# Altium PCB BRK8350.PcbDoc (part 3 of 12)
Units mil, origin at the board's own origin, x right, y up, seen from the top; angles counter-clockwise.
Board outline 9448.82 x 5905.51 mil, 8 copper layers (L1-TOP, L2-GND, L3-SIG, L4-GND, L5-PWR, L6-PWR, L7-GND, L8-BOT), stack 57.69 mil thick; 288 components, 543 nets, 1891 pads, 2032 vias.
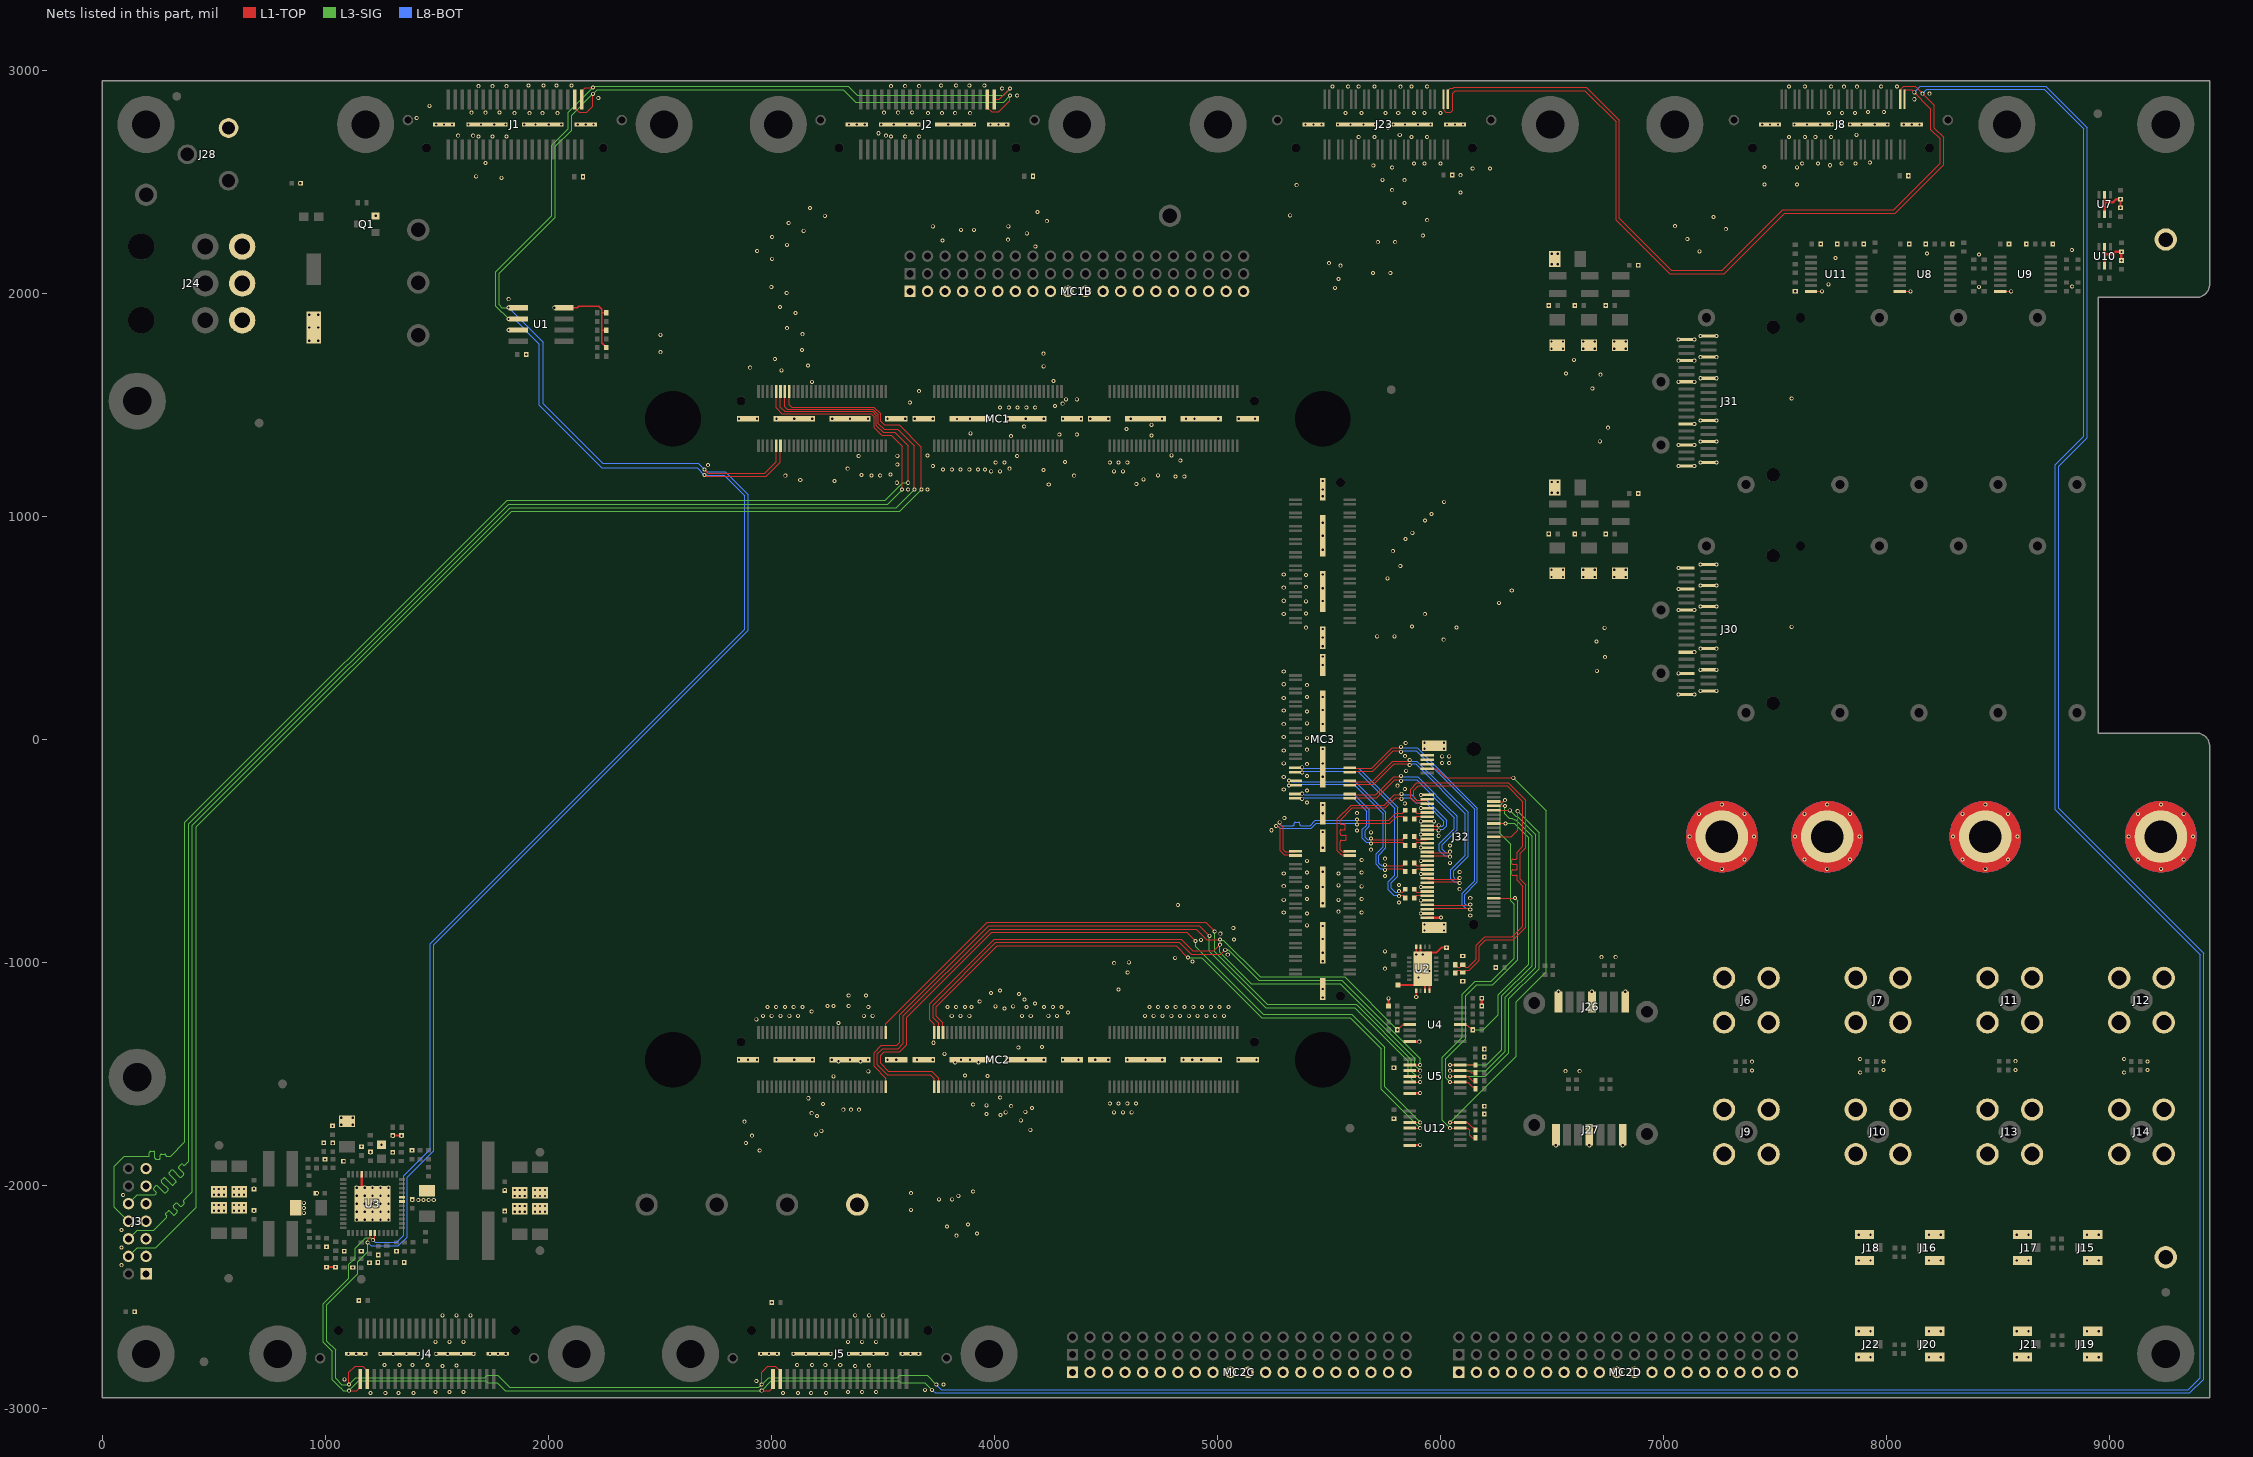
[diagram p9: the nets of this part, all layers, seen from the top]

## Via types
v1: diameter 18, hole 10, L1-TOP to L8-BOT, tented both sides, 2032 vias

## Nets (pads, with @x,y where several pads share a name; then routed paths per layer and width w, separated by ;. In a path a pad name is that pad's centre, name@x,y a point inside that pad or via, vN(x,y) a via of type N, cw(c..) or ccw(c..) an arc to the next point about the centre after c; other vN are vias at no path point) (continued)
DGND: C1.1 C2.1 C3.1 C4.1 C5.1 C30.1 C31.1 C32.1 C33.2 C34.2 C36.2 C37.1 C38.1 C39.1 C40.1 C42.2 C43.2 C44.2 C46.2 C47.2 C48.1 C49.1 C50.1 C51.1 C53.2 C54.2 C55.2 C57.2 C58.2 C59.1 C60.1 C61.1 C63.2 C64.2 C65.2 C67.1 C68.1 C69.1 C72.2 C73.1 C74.2 C75.1 C76.1 C85.1 C86.1 C87.1 C88.1 C89.1 C90.1 C91.1 C92.1 C93.1 C94.1 C95.1 C96.1 C97.1 C98.1 C99.1 C100.1 C101.1 C102.1 C103.1 C104.1 C105.1 C106.1 C107.1 C108.1 C109.1 C110.1 C111.1 C112.1 C113.1 C114.1 C115.1 C116.1 C117.1 C118.1 C119.1 J1.0 J2.0 J3.1 J3.3 J3.5 J3.7 J3.9 J3.11 J3.13 J4.0 J5.0 J6.2 J7.2 J8.0 J9.2 J10.2 J11.2 J12.2 J13.2 J14.2 J15.2 J16.2 J17.2 J18.2 J19.2 J20.2 J21.2 J22.2 J23.0 J24.4 J24.5 J24.6 J26.1 J26.4 J26.7 J27.1 J27.4 J27.7 J28.2 J30.1 J30.4 J30.7 J30.13 J30.16 J30.19 J30.20 J30.23 J30.26 J30.32 J30.35 J30.38 J31.1 J31.4 J31.7 J31.13 J31.16 J31.19 J31.20 J31.23 J31.26 J31.32 J31.35 J31.38 J32.1 J32.3 J32.9 J32.15 J32.21 J32.27 J32.33 J32.39 J32.45 J32.51 J32.57 J32.71 J32.73 J32.75 MC1.0 MC1B.1 MC1B.2 MC1B.3 MC1B.4 MC1B.5 MC1B.6 MC1B.7 MC1B.8 MC1B.9 MC1B.10 MC1B.11 MC1B.12 MC1B.13 MC1B.14 MC1B.15 MC1B.16 MC1B.17 MC1B.18 MC1B.19 MC1B.20 MC2.0 MC2C.1 MC2C.2 MC2C.3 MC2C.4 MC2C.5 MC2C.6 MC2C.7 MC2C.8 MC2C.9 MC2C.10 MC2C.11 MC2C.12 MC2C.13 MC2C.14 MC2C.15 MC2C.16 MC2C.17 MC2C.18 MC2C.19 MC2C.20 MC2D.1 MC2D.2 MC2D.3 MC2D.4 MC2D.5 MC2D.6 MC2D.7 MC2D.8 MC2D.9 MC2D.10 MC2D.11 MC2D.12 MC2D.13 MC2D.14 MC2D.15 MC2D.16 MC2D.17 MC2D.18 MC2D.19 MC2D.20 MC3.0 Q1.2 R1.1 R2.1 R6.1 R7.1 R8.1 R9.1 R10.1 R12.1 R13.1 R17.1 R20.1 R24.1 R25.1 R28.1 R29.1 R59.1 R60.1 R63.1 R66.1 SO1.1 SO2.1 SO3.1 SO4.1 TP10.1 TP13.1 TP15.1 U1.4 U1.7 U2.1 U2.3 U2.4 U2.13 U2.14 U2.PAD U3.7 U3.8 U3.21 U3.PAD U4.7 U5.7 U7.2 U7.5 U8.7 U9.7 U10.2 U10.5 U11.7 U12.7 | length 8888.9
  L1-TOP w5: U11.7@7661.42,2007.87 v1(7710.63,2007.87) ; U8.7@8059.06,2007.87 v1(8108.27,2007.87) ; U9.7@8509.84,2007.87 v1(8559.06,2007.87)
  L1-TOP w8: v1(1005.74,-2366.85) 1005.8,-2366.8 1045.69,-2366.8 v1(1045.74,-2366.74) ; R28.1@1161.47,-2294.3 v1(1161.74,-2294.58) ; v1(1303.27,-1778.55) 1305.24,-1776.58 1340.77,-1776.58 v1(1342.74,-1778.55) ; U1.4@2070.42,1934.26 2129.92,1934.26 2136.61,1940.94 2226.38,1940.94 2240.12,1927.2 2240.12,1911.54 ; R6.1@2259.84,1755.54 2259.84,1757.5 2240.12,1777.22 2240.12,1833.54 ; R7.1@2259.84,1833.54 2240.12,1833.54 ; R8.1@2259.84,1911.54 2240.12,1911.54 ; C88.1@5809.83,-1102.49 C88.1@5810.1,-1102.22 5883.92,-1102.22 5891.73,-1094.41 5921.26,-1064.88 U2.PAD@5921.26,-1029.53 ; v1(5891.73,-1156.5) U2.1@5891.73,-1127.95 ; U2.14@5891.73,-931.1 5891.73,-1000 U2.PAD@5911.42,-1019.69 ; U2.13@5911.42,-931.1 U2.PAD@5911.42,-1019.69 ; v1(5921.26,-965.55) 5930.06,-956.76 5981.43,-956.76 6003.54,-934.65 v1(6027.56,-934.65) ; U2.3@5931.1,-1127.95 U2.PAD@5931.1,-1039.37 ; U2.4@5950.79,-1127.95 5950.79,-1059.06 U2.PAD@5931.1,-1039.37 ; 2240.12,1833.54 2240.12,1911.54 ; U2.PAD@5911.42,-1019.69 U2.PAD@5921.26,-1029.53 ; U2.PAD@5921.26,-1029.53 U2.PAD@5931.1,-1039.37
  L1-TOP w10: U12.7@5863.19,-1820.87 5864.17,-1819.88 5908.46,-1819.88 v1(5909.45,-1818.9) ; U5.7@5863.19,-1588.58 5864.17,-1587.6 5908.46,-1587.6 v1(5909.45,-1586.61) ; U4.7@5863.19,-1356.3 v1(5905.51,-1356.3) ; U2.PAD@5891.73,-1094.41 U2.PAD@5894.65,-1091.5
  L1-TOP w11: U3.21@1163.53,-1950.77 1163.53,-2033.45 v1(1212.74,-2082.66) ; C75.1@5767.32,-1196.85 v1(5767.32,-1161.81) ; v1(6185.43,-1196.85) v1(6185.43,-1161.42) ; U10.5@8978.35,2122.05 8978.35,2174.82 ; U10.2@8978.35,2208.66 8978.35,2174.82 ; U7.5@8978.35,2354.33 8978.35,2407.1 ; U7.2@8978.35,2440.94 8978.35,2407.1 ; v1(9049.21,2382.28) v1(9049.21,2420.87) 9029.54,2420.87 9015.78,2407.1 8978.35,2407.1 ; v1(9053.15,2146.06) v1(9053.15,2184.65) 9025.6,2184.65 9015.78,2174.82 8978.35,2174.82
  L1-TOP w12: J32.1@5941.93,-801.18 5998.75,-801.18 6000.66,-799.27 v1(6002.28,-799.27)
  L1-TOP w14: MC2.0@4087.79,-1431.39 4093.39,-1436.99 v1(4140.76,-1436.99) 4173.88,-1436.99 MC2.0@4179.48,-1431.39 ; v1(4678.17,-1436.99) MC2.0@4724.98,-1436.99
  L1-TOP w16: v1(3890.76,1437.02) 3930.1,1437.02 MC1.0@3934.69,1441.62
  L1-TOP w60: 7391.81,-437.01 ccw(c7261.81,-437.01) 7391.81,-437.01 ; 7864.25,-437.01 ccw(c7734.25,-437.01) 7864.25,-437.01 ; 8572.91,-437.01 ccw(c8442.91,-437.01) 8572.91,-437.01 ; 9360.31,-437.01 ccw(c9230.31,-437.01) 9360.31,-437.01
  L8-BOT w60: 7391.81,-437.01 ccw(c7261.81,-437.01) 7391.81,-437.01 ; 7864.25,-437.01 ccw(c7734.25,-437.01) 7864.25,-437.01 ; 8572.91,-437.01 ccw(c8442.91,-437.01) 8572.91,-437.01 ; 9360.31,-437.01 ccw(c9230.31,-437.01) 9360.31,-437.01
  other v1: 1202.6,-2931.11 1269.78,-2931.11 1328.6,-2931.11 1395.78,-2931.11 3052.99,-2931.11 3120.18,-2931.11 3178.99,-2931.11 3246.18,-2931.11 1494.19,-2927.38 1557.19,-2927.38 1620.19,-2927.38 3344.58,-2927.38 3407.58,-2927.38 3470.58,-2927.38 3689.06,-2917.32 3771.65,-2893.7 2933.07,-2877.95 1086.61,-2870.08 1525.69,-2810.05 3376.08,-2810.05 1588.64,-2808.65 3439.03,-2808.65 1265.7,-2806.32 1332.88,-2806.32 1391.7,-2806.32 1458.88,-2806.32 3116.09,-2806.32 3183.28,-2806.32 3242.09,-2806.32 3309.28,-2806.32 7875.22,-2770.67 7927.93,-2770.67 8190.18,-2770.67 8242.89,-2770.67 8583.88,-2770.67 8636.59,-2770.67 8898.84,-2770.67 8951.55,-2770.67 1104.01,-2755.97 1139.24,-2755.91 1175.01,-2755.97 1249.01,-2755.97 1305.01,-2755.97 1364.01,-2755.97 1415.01,-2755.97 1498.47,-2755.86 1549.47,-2755.86 1608.47,-2755.86 1664.47,-2755.86 1738.47,-2755.86 1774.24,-2755.91 1809.47,-2755.86 2954.4,-2755.97 2989.64,-2755.91 3025.4,-2755.97 3099.4,-2755.97 3155.4,-2755.97 3214.4,-2755.97 3265.4,-2755.97 3348.87,-2755.86 3399.87,-2755.86 3458.87,-2755.86 3514.87,-2755.86 3588.87,-2755.86 3624.64,-2755.91 3659.87,-2755.86 1494.19,-2701.78 1557.19,-2701.78 1620.19,-2701.78 3344.58,-2701.78 3407.58,-2701.78 3470.58,-2701.78 7875.22,-2654.53 7927.93,-2654.53 8190.18,-2654.53 8242.89,-2654.53 8583.88,-2654.53 8636.59,-2654.53 8898.84,-2654.53 8951.55,-2654.53 1525.64,-2583.05 1588.64,-2583.05 1651.64,-2583.05 3376.03,-2583.05 3439.03,-2583.05 3502.03,-2583.05 145.37,-2566.93 3002.03,-2525.76 1151.31,-2516.76 1123.54,-2368.85 86.61,-2358.27 1198.74,-2347.24 1236.66,-2345.66 1353.82,-2345.66 7875.22,-2337.6 7927.93,-2337.6 8190.18,-2337.6 8242.89,-2337.6 8583.88,-2337.6 8636.59,-2337.6 8898.84,-2337.6 8951.55,-2337.6 1237.84,-2312.74 1319.47,-2295.99 1085.74,-2294.27 86.61,-2279.53 1005.74,-2276.35 3830.14,-2225.96 7875.22,-2221.46 7927.93,-2221.46 8190.18,-2221.46 8242.89,-2221.46 8583.88,-2221.46 8636.59,-2221.46 8898.84,-2221.46 8951.55,-2221.46 3922.12,-2216.54 86.61,-2200.79 3787.4,-2185.11 3881.84,-2175.83 1141.09,-2154.32 1176.92,-2154.32 1212.74,-2154.32 1248.57,-2154.32 1284.39,-2154.32 904.27,-2123.66 1141.09,-2118.49 1176.92,-2118.49 1212.74,-2118.49 1248.57,-2118.49 1284.39,-2118.49 1850.27,-2118.66 1872.27,-2118.66 1895.27,-2118.66 1940.79,-2118.91 1962.79,-2118.91 1985.79,-2118.91 1805.27,-2117.55 501.14,-2114.54 523.14,-2114.54 546.14,-2114.54 591.32,-2114.54 613.32,-2114.54 636.32,-2114.54 680.32,-2114.43 3625.98,-2110.24 904.27,-2101.66 1850.27,-2092.66 1872.27,-2092.66 1895.27,-2092.66 1940.79,-2092.91 1962.79,-2092.91 1985.79,-2092.91 501.14,-2088.54 523.14,-2088.54 546.14,-2088.54 591.32,-2088.54 613.32,-2088.54 636.32,-2088.54 1141.09,-2082.66 1176.92,-2082.66 1248.57,-2082.66 1284.39,-2082.66 904.27,-2078.66 1390.74,-2066.3 1417.74,-2066.3 1440.74,-2066.3 1463.99,-2066.3 1486.74,-2066.3 3751.97,-2062.99 3811.02,-2062.99 1850.27,-2047.66 1872.27,-2047.66 1895.27,-2047.66 1940.79,-2047.66 1962.79,-2047.66 1985.79,-2047.66 3838.58,-2047.24 1141.09,-2046.84 1176.92,-2046.84 1212.74,-2046.84 1248.57,-2046.84 1284.39,-2046.84 94.49,-2043.31 501.14,-2042.6 523.14,-2042.6 546.14,-2042.6 591.32,-2042.54 613.32,-2042.54 636.32,-2042.54 963.27,-2035.66 3625.98,-2035.43 3905.51,-2027.56 1805.27,-2021.77 1850.27,-2021.66 1872.27,-2021.66 1895.27,-2021.66 1940.79,-2021.66 1962.79,-2021.66 1985.79,-2021.66 501.14,-2016.6 523.14,-2016.6 546.14,-2016.6 591.32,-2016.54 613.32,-2016.54 636.32,-2016.54 680.32,-2015.54 1141.09,-2011.01 1176.92,-2011.01 1212.74,-2011.01 1248.57,-2011.01 1284.39,-2011.01 1082.98,-1892.66 998.74,-1884.95 1302.74,-1853.55 1202.74,-1852.55 2947.91,-1844.78 1388.74,-1843.98 1162.74,-1826.58 6517.52,-1820.87 6667.52,-1820.87 6817.52,-1820.87 1252.74,-1818.17 1033.74,-1811.55 993.74,-1810.55 2885.81,-1811.01 2913.39,-1777.98 3200.79,-1771.65 3224.41,-1755.91 4161.42,-1751.25 1033.1,-1734.96 1072.29,-1729.16 1123.9,-1729.16 2879.62,-1715.13 4118.58,-1708.66 5791.34,-1701.18 1072.29,-1696.99 1123.9,-1696.99 3204.72,-1688.98 4027.56,-1685.04 3964.57,-1681.1 6197.24,-1681.1 3181.1,-1677.17 4051.18,-1673.23 4537.09,-1673.2 4576.46,-1673.2 4615.83,-1673.2 4139.1,-1670.86 3322.83,-1661.42 3357.19,-1661.09 3393.7,-1661.09 4169.29,-1653.54 4075.83,-1645.73 6197.24,-1645.67 3964.57,-1641.73 3905.51,-1637.8 3232.3,-1636.13 4517.73,-1633.83 4557.1,-1633.83 4596.47,-1633.83 4635.84,-1633.83 3166.24,-1609.94 4026.33,-1606.29 3279.53,-1511.39 3969.57,-1509.79 3868.11,-1508.39 7881.89,-1494.74 9065.62,-1494.74 3435.06,-1489.35 6560.32,-1488.57 6624.46,-1488.42 7396.92,-1485.08 7986.3,-1483.91 9170.03,-1483.91 8578.4,-1482.91 5791.34,-1472.83 3824.8,-1449.34 3929.13,-1448.82 7396.92,-1446.08 3301.16,-1444.35 3399.58,-1444.35 7986.3,-1444.91 9170.03,-1444.91 8578.4,-1443.91 2855.67,-1436.99 2895.88,-1436.99 2936.09,-1436.99 3022.94,-1436.99 3103.36,-1436.99 3183.79,-1436.99 3271.65,-1436.99 3353.36,-1436.99 3433.79,-1436.99 3520.63,-1436.99 3560.84,-1436.99 3653.54,-1437.01 3723.5,-1436.99 3850.39,-1437.01 3890.76,-1436.99 3964.57,-1437.01 4060.34,-1436.99 4221.19,-1436.99 4308.03,-1436.99 4377.95,-1437.01 4452.76,-1437.01 4510.9,-1436.99 4597.74,-1436.99 4753.12,-1436.99 4847.74,-1436.99 4887.95,-1436.99 4928.17,-1436.99 5008.59,-1436.99 5095.43,-1436.99 5175.86,-1436.99 7881.89,-1434.08 9065.62,-1434.08 6197.24,-1425.2 3776.68,-1410.8 6197.24,-1389.76 4107.67,-1382.81 4214.2,-1380 3727.72,-1361.14 3302.04,-1272.16 2933.07,-1255.91 2962.61,-1240.26 3001.98,-1240.26 3041.26,-1240.26 3080.72,-1240.26 3120,-1240.26 3415.11,-1240.42 3454.58,-1240.42 3809.17,-1240.16 3848.44,-1240.16 3887.91,-1240.16 4124.13,-1240.16 4163.4,-1240.16 4242.24,-1240.16 4281.51,-1240.16 4675.21,-1240.16 4714.68,-1240.16 4753.95,-1240.16 4793.42,-1240.16 4832.69,-1240.16 4872.16,-1240.16 4911.43,-1240.16 4950.9,-1240.16 4990.17,-1240.16 5029.64,-1240.16 4330.71,-1225.69 3181.1,-1220.47 4045.29,-1207.96 2982.53,-1200.89 3021.9,-1200.89 3061.37,-1200.79 3100.64,-1200.89 3140.11,-1200.79 3435.22,-1200.95 3789.72,-1200.79 3829.09,-1200.79 3868.46,-1200.79 3897.64,-1200.89 4144.05,-1200.79 4222.79,-1200.79 4262.16,-1200.79 4301.53,-1200.79 4695.23,-1200.79 4734.6,-1200.79 4773.97,-1200.79 4813.34,-1200.79 4852.71,-1200.79 4892.08,-1200.79 4931.45,-1200.79 4970.82,-1200.79 5010.19,-1200.79 5049.56,-1200.79 4005.36,-1198 4084.5,-1197.85 3251.97,-1196.85 3279.53,-1196.85 3347.01,-1196.85 4182.83,-1185.19 3934.36,-1175.6 4134.99,-1166.8 5472.46,-1157.79 3347.01,-1149.61 3424.67,-1149.61 4110.26,-1142.06 3985.61,-1137.74 6528.94,-1132.13 6678.94,-1132.13 6828.94,-1132.13 4025.3,-1126.3 4557.09,-1122.05 5472.46,-1119.87 6100.24,-1085.57 5901.57,-1068.11 4597.95,-1045.7 5901.57,-1039.37 5950.79,-1039.37 5751.97,-1028.99 6248.03,-1023.62 4537.55,-1004.27 4603.23,-1000.29 4888.18,-997.2 5472.46,-996.06 4811.02,-980.32 6721.74,-977.46 6785.88,-977.31 6100.24,-972.04 5046.63,-966.24 5891.73,-965.55 5472.46,-957.98 5751.97,-951.33 4926.53,-899.58 5074.86,-898.51 5472.72,-895.98 5013.03,-872 5928.5,-858.27 6016.39,-858.27 5071.66,-847.16 5472.72,-837.98 5401.72,-834.65 5928.5,-830.71 6016.39,-830.71 6133.86,-790.8 5401.72,-781.54 5912.39,-781.5 5297.67,-777.42 5647.24,-777.67 5543.2,-773.55 4822.83,-744.09 5472.33,-735.6 5814.96,-731.74 5912.39,-722.44 5297.67,-720.47 5543.2,-720.44 5401.72,-716.54 5647.24,-716.5 6133.86,-713.14 6086.61,-672.69 5401.72,-663.43 5912.39,-663.39 5472.46,-662.39 5297.67,-659.31 5647.24,-659.56 5543.2,-655.44 5814.96,-654.08 5751.97,-613.34 5912.39,-604.33 5297.67,-602.36 5543.2,-602.33 5401.72,-598.43 5647.24,-598.39 5472.72,-594.98 6086.61,-595.03 7261.81,-581.35 7734.25,-581.35 8442.91,-581.35 9230.31,-581.35 6043.31,-554.58 5401.72,-545.32 5912.39,-545.28 5647.24,-541.44 7159.75,-539.07 7363.87,-539.07 7632.19,-539.07 7836.31,-539.07 8340.85,-539.07 8544.98,-539.07 9128.25,-539.07 9332.38,-539.07 5751.97,-535.68 5688.98,-495.52 5472.46,-486.39 5912.39,-486.22 6043.31,-476.92 7117.47,-437.01 7406.15,-437.01 7589.91,-437.01 7878.59,-437.01 8298.57,-437.01 8587.25,-437.01 9085.98,-437.01 9374.65,-437.01 5992.13,-433.07 5912.39,-427.17 5688.98,-417.86 5472.46,-416.39 5625.98,-409.7 5243.06,-408.41 5912.39,-368.11 5971.47,-368.11 5300.25,-353.3 7159.75,-334.95 7363.87,-334.95 7632.19,-334.95 7836.31,-334.95 8340.85,-334.95 8544.98,-334.95 9128.25,-334.95 9332.38,-334.95 5472.46,-332.46 5625.98,-332.03 5912.39,-309.06 5472.46,-295.28 7261.81,-292.67 7734.25,-292.67 8442.91,-292.67 9230.31,-292.67 5840.67,-288.93 5401.72,-283.46 5912.39,-250.01 5401.72,-230.36 5297.67,-226.24 5840.67,-223.28 5807.37,-208.41 5297.67,-169.29 5472.72,-168.98 5401.72,-165.35 5846.46,-141.73 5401.72,-112.25 5297.67,-108.13 5472.72,-108.98 6007.87,-106.3 6039.37,-106.3 5840.88,-76.33 6007.87,-76.77 6039.37,-76.77 5297.67,-51.18 5401.72,-47.24 5472.44,-44.49 5928.5,-43.31 6016.39,-43.31 5844.39,-17.09 5928.5,-15.75 6016.39,-15.75 5401.72,5.86 5297.67,9.98 5297.67,66.93 5472.46,68.02 5401.72,70.87 5401.72,123.97 5297.67,128.09 5472.72,131.02 5297.67,185.04 5401.72,188.98 5472.46,189.02 7067.69,200.79 7138.61,200.79 7166.5,216.54 7237.43,216.54 5401.72,242.08 5297.67,246.2 7067.69,295.28 5297.67,303.15 6701.07,306.32 7166.5,311.02 7237.43,311.02 5472.46,332.5 6738.09,367.73 5472.46,371.02 7138.61,389.76 7166.5,405.51 7237.43,405.51 5472.46,417.02 6699.61,438.04 6014.71,445.92 5472.44,455.52 5716.54,461.3 5794.2,461.3 5472.46,494.02 6736.63,499.45 5397.64,500 6071.9,501.04 7574.82,503.94 5872.98,504.97 5930.17,560.09 5297.67,560.99 5397.64,563.02 7067.69,578.74 7138.61,578.74 7166.5,594.49 7237.43,594.49 6262.74,611.27 5397.64,618.11 5297.67,620.57 5472.46,620.02 6319.93,666.39 7067.69,673.23 5472.46,677.02 5297.67,679.1 5397.64,681.13 7166.5,688.98 7237.43,688.98 5763.26,720.99 6497.61,726.92 6549.61,726.92 6640.32,726.92 6692.32,726.92 6779.1,726.92 6831.1,726.92 5397.64,736.22 5297.67,738.15 5472.46,738.02 6497.61,759.84 6549.61,759.84 6640.32,759.84 6692.32,759.84 6779.1,759.84 6831.1,759.84 7067.69,767.72 5820.45,776.11 7166.5,783.46 7237.43,783.46 5786.76,842.52 5472.2,849.42 5843.95,897.64 5472.46,912.42 6486.02,920.53 6602.94,920.17 6741.72,920.17 5874.02,925.2 5472.2,970.42 5931.21,980.31 5959.59,1008.91 6016.78,1064.03 5472.46,1089.02 6887.19,1101.28 6499,1105.21 6526.56,1105.21 3613.94,1118.83 3700.79,1118.83 5472.46,1119.9 4244.09,1141.73 4636.81,1143.7 3562.99,1149.61 6499,1152.46 6526.17,1152.46 3283.46,1157.48 5472.46,1157.02 3129.92,1161.42 4668.59,1165.01 4812.73,1177.71 4852.1,1177.71 3062.99,1181.1 3448.82,1181.85 3488.19,1181.85 4358.27,1181.1 4734.25,1183.07 3405.01,1184.87 3535.02,1186.69 4537.09,1200.82 4576.46,1200.82 3986.01,1200.92 4025.38,1200.92 4220.1,1207.31 3769.84,1209.41 3809.24,1209.38 3848.58,1209.41 3887.98,1209.38 3927.35,1209.38 3957.68,1209.38 3342.52,1212.6 4068.52,1212.6 3724.41,1224.41 7067.67,1224.41 7138.6,1224.41 2716.19,1228.35 3564.91,1231.25 4006.02,1240.29 4045.39,1240.29 4517.73,1240.19 4557.1,1240.19 4596.47,1240.19 7166.49,1240.16 7237.42,1240.16 4317.02,1242.05 4833.97,1249.89 3392.14,1269.28 4102.72,1269.76 3564.91,1270.28 3700.79,1271.65 4794.15,1272.53 7067.67,1318.9 7138.6,1318.9 7166.49,1334.65 7237.42,1334.65 6714.67,1335.2 4074.8,1358.27 4704.24,1360.93 4291.34,1366.14 4370.08,1366.14 3893.44,1371.28 4592.63,1390.3 6751.69,1396.6 4133.86,1401.57 4704.72,1409.45 7138.6,1413.39 7166.49,1429.13 7237.42,1429.13 3833,1436 2855.67,1437.02 2936.09,1437.02 3022.94,1437.02 3103.36,1437.02 3183.79,1437.02 3272.94,1437.02 3353.36,1437.02 3433.79,1437.02 3520.63,1437.02 3601.06,1437.02 3643.07,1437.02 3723.5,1437.02 3971.19,1437.02 4060.34,1437.02 4140.76,1437.02 4221.19,1437.02 4308.03,1437.02 4388.46,1437.02 4430.47,1437.02 4510.9,1437.02 4611.26,1437.02 4751.97,1437.02 4859.55,1437.01 4897.64,1437.01 5003.94,1437.01 5095.43,1437.02 5169.29,1437.01 4025.59,1487.2 4064.96,1487.2 4104.33,1487.2 4143.7,1487.2 4183.07,1487.2 4271.6,1493.22 4306.51,1504.21 3620.95,1509.45 4321.93,1523.61 4369.81,1523.61 7574.8,1527.56 3662.52,1560 6681.1,1572.45 3183.17,1602.3 7067.67,1602.36 7138.6,1602.36 4265.75,1605.32 7166.49,1618.11 7237.42,1618.11 6718.12,1633.86 6562.99,1639.13 3046.26,1653.54 2905.51,1665.35 4221.52,1671.76 3165.12,1675.63 7067.67,1696.85 7138.6,1696.85 6598.69,1700.79 3015.75,1704.72 7166.49,1712.6 7237.42,1712.6 1901.97,1724.41 4220.47,1728.35 2503.94,1735.19 3138.31,1744.61 6497.59,1750.54 6549.59,1750.54 6640.31,1750.54 6692.31,1750.54 6779.09,1750.54 6831.09,1750.54 6497.59,1783.46 6549.59,1783.46 6640.31,1783.46 6692.31,1783.46 6779.09,1783.46 6831.09,1783.46 928.5,1786.47 968.5,1786.47 7067.67,1791.34 7138.6,1791.34 7166.49,1807.09 7237.42,1807.09 2503.94,1812.85 3139.85,1815.71 1821.99,1834.26 3070.87,1842.52 928.5,1845.47 968.5,1845.47 928.5,1902.97 968.5,1902.97 3108.36,1910.2 2027.11,1934.26 3039.37,1937.01 6602.92,1943.8 6741.7,1943.8 6486,1944.15 1822.83,1972.44 3068.99,2000.75 7590.55,2007.87 5527.56,2023.62 3000,2027.56 8415.15,2028 8832.69,2029.09 7740.16,2039.37 5543.03,2063.14 5697.68,2090.11 5775.35,2090.11 5551.9,2122.96 6887.17,2124.9 6498.98,2128.83 6526.54,2128.83 5500,2133.86 3003.94,2153.54 7771.65,2157.48 8415.37,2173.01 6498.98,2176.08 6526.15,2176.08 8181.1,2177.17 7161.94,2187.42 2937.01,2188.98 8830.71,2192.91 4183.7,2208.96 3070.87,2216.54 7704.86,2219.62 7778.87,2219.62 7897.77,2219.62 8102.5,2219.65 8176.51,2219.65 8295.41,2219.65 8549.37,2220.58 8627.32,2220.58 8746.22,2220.58 5719.44,2228.35 5797.1,2228.35 3767.72,2236.22 4061.75,2239.38 7106.82,2242.54 3003.94,2251.97 5921.26,2258.02 4145.67,2267.72 3145.23,2279.09 3850.39,2283.46 3909.45,2283.46 7279.61,2286.28 3724.41,2299.21 4062.99,2299.21 7051.7,2299.73 3078.3,2314.52 4235.37,2322.2 5940.94,2326.77 7224.49,2341.4 1226.43,2346.32 3240.16,2346.46 5326.77,2348.43 4193.36,2363.02 3173.23,2381.89 5839.1,2403.96 6090.55,2450.93 5783.98,2461.15 5355.59,2483.76 7598.43,2486.36 7452.76,2487.15 888.19,2492.13 5839.1,2506.32 5740.16,2507.87 1791.03,2516.84 2155.91,2521.24 1677.14,2523.62 4173.23,2523.62 8098.18,2525.87 6053.31,2528.87 6090.55,2528.59 6144.63,2559.06 6222.3,2559.06 5783.98,2563.51 7452.76,2564.82 7598.43,2564.03 5699.47,2571.4 7747.07,2573.09 5882.2,2581.1 5929.13,2581.1 6000.31,2581.1 7622.05,2581.1 7693.23,2581.1 7799.21,2581.1 7861.52,2581.1 1718.55,2583.05 7925.2,2585.63 5633.86,2699.97 5704.72,2699.97 5870.08,2699.97 5940.94,2699.97 7562.99,2699.97 7633.86,2699.97 7681.1,2699.97 7751.97,2699.97 1687,2701.77 1750,2701.77 1813,2701.77 3537.39,2701.77 3600.39,2701.77 3663.39,2701.77 1596.4,2705.5 1663.59,2705.5 3513.98,2705.5 5817.8,2709.32 7865.04,2709.32 3480.32,2716.54 5764.08,2741.51 1497.71,2755.85 1568.71,2755.85 1642.71,2755.85 1698.71,2755.85 1757.71,2755.85 1808.71,2755.85 3348.1,2755.85 3419.1,2755.85 3493.1,2755.85 3549.1,2755.85 3608.1,2755.85 3659.1,2755.85 1532.94,2755.91 1892.18,2755.96 1943.18,2755.96 2002.18,2755.96 2058.18,2755.96 2132.18,2755.96 2167.94,2755.91 2203.18,2755.96 3383.34,2755.91 3793.57,2755.96 3852.57,2755.96 3908.57,2755.96 3982.57,2755.96 4018.34,2755.91 4053.57,2755.96 5395.65,2755.97 5430.88,2756.02 5466.65,2755.97 5540.65,2755.97 5596.65,2755.97 5655.65,2755.97 5706.65,2755.97 5790.12,2756.08 5841.12,2756.08 5900.12,2756.08 5956.12,2756.08 6030.12,2756.08 6065.88,2756.02 6101.12,2756.08 7442.9,2755.97 7478.13,2756.02 7513.9,2755.97 7587.9,2755.97 7643.9,2755.97 7702.9,2755.97 7753.9,2755.97 7837.36,2756.08 7888.36,2756.08 7947.36,2756.08 8003.36,2756.08 8077.36,2756.08 8113.13,2756.02 8148.36,2756.08 1410.33,2784.45 1848.3,2806.31 1915.49,2806.31 1974.3,2806.31 2041.49,2806.31 3702.63,2806.31 3765.88,2806.31 3824.7,2806.31 3891.88,2806.31 5574.8,2807.09 5645.98,2807.09 5754.21,2807.09 5811.02,2807.09 5882.2,2807.09 5929.13,2807.09 6000.31,2807.09 7742.4,2807.09 7801.45,2807.09 7858.27,2807.09 1655.55,2808.65 1718.55,2808.65 3505.94,2808.65 3568.94,2808.65 1781.5,2810.04 3631.89,2810.04 7917.32,2812.07 7988.19,2812.07 1467.52,2839.57 8124.57,2869.02 2224.41,2874.02 4102.36,2885.83 8192.91,2893.7 4035.47,2917.32 5820.91,2925.2 7809.1,2925.2 7868.15,2925.2 5515.75,2925.96 5586.61,2925.96 5633.86,2925.96 5704.72,2925.96 5870.08,2925.96 5940.94,2925.96 7562.99,2925.96 7633.86,2925.96 7751.97,2925.96 7976.38,2925.96 8047.24,2925.96 1687,2927.37 1750,2927.37 1813,2927.37 3537.39,2927.37 3600.39,2927.37 3663.39,2927.37 1911.4,2931.1 1978.59,2931.1 2037.4,2931.1 2104.59,2931.1 3761.8,2931.1 3828.98,2931.1 3887.8,2931.1 3954.98,2931.1
I2C_SCL: J1.1@2149.69,2868.71 J2.1@4000.09,2868.71 J4.1@1157.44,-2868.71 J5.1@3007.84,-2868.71 J8.1@8080.87,2869.02 J23.1@6033.62,2869.02 MC1.12 U1.6 U3.43 | length 29224.4
  L1-TOP w5: v1(1106.54,-2921.12) 1141.83,-2921.12 1157.49,-2905.46 J4.1@1157.49,-2868.71 ; v1(1213.74,-2246.16) 1222.58,-2237.32 U3.43@1222.58,-2214.55 ; J1.1@2149.69,2868.71 2149.69,2905.46 2165.35,2921.12 v1(2200.64,2921.12) ; v1(2700.35,1183.84) 2703.87,1183.84 2709.45,1178.25 2977.85,1178.25 3041.35,1241.76 MC1.12@3041.35,1315.37 ; v1(2956.94,-2921.12) 2992.23,-2921.12 3007.89,-2905.46 J5.1@3007.89,-2868.71 ; J2.1@4000.09,2868.71 4022.25,2868.71 v1(4070.87,2917.32) ; J23.1@6033.62,2869.02 6033.62,2908.19 6044.44,2919.01 6057.67,2919.01 6060.53,2921.87 6654.46,2921.87 6802.4,2773.93 6802.4,2335.76 7035.8,2102.36 7263.78,2102.36 7535.43,2374.02 8031.5,2374.02 8240.16,2582.68 8240.16,2692.42 8199.58,2733 8199.58,2825.1 8112.5,2912.19 8086.81,2912.19 8085.82,2911.2 8083.88,2911.2 8080.87,2908.19 J8.1@8080.87,2869.02
  L3-SIG w5: v1(1213.74,-2246.16) 1203.8,-2236.22 1182.68,-2236.22 1135.35,-2283.55 1135.35,-2326.36 1106.42,-2355.29 1106.42,-2415.94 992.13,-2530.23 992.13,-2704.72 1031.5,-2744.09 1031.5,-2871.13 1032.24,-2871.88 1032.24,-2872.36 1068.45,-2908.57 1068.93,-2908.57 1081.49,-2921.12 v1(1106.54,-2921.12) 1150.46,-2877.2 1720.67,-2877.2 1729.38,-2885.91 1771.73,-2885.91 1806.95,-2921.12 v1(2956.94,-2921.12) 3000.86,-2877.2 3571.07,-2877.2 3579.77,-2885.91 3689.06,-2885.91 v1(3720.47,-2917.32) ; v1(1822.49,1883.76) 1764.53,1941.72 1764.53,2095.24 2016.5,2347.2 2016.5,2552.17 2016.5,2663.63 2090.14,2737.28 2090.14,2810.62 v1(2200.64,2921.12) 2204.16,2921.12 2209.58,2926.54 3344.41,2926.54 3384.98,2885.97 4042.74,2885.97 4070.16,2913.39 v1@4070.87,2913.39
  L8-BOT w5: v1(1213.74,-2246.16) 1215.16,-2246.16 1225.01,-2256.02 1320.39,-2256.02 1351.39,-2225.01 1351.39,-1957.9 1470.76,-1838.54 1470.76,-916.49 2880,492.75 2880,1091.03 2788.19,1182.84 2701.35,1182.84 v1(2700.35,1183.84) 2667.65,1216.54 2240.16,1216.54 1960.63,1496.06 1960.63,1771.65 1848.52,1883.76 v1(1822.49,1883.76) ; v1(3720.47,-2917.32) 3734.45,-2931.3 9360.04,-2931.3 9422.21,-2869.13 9422.21,-960.47 8772.44,-310.71 8772.44,1223.8 8897.01,1348.38 8897.01,1348.51 8900.33,1351.82 8900.33,2742.23 8714.67,2927.89 8152.34,2927.89 v1(8124.57,2900.12)
I2C_SDA: J1.3 J2.3 J4.3 J5.3 J8.3 J23.3 MC1.10 U1.5 U3.42 | length 29677.4
  L1-TOP w5: v1(1106.54,-2893.57) 1106.54,-2838.45 1133.96,-2811.03 1168.06,-2811.03 1188.99,-2831.96 J4.3@1188.99,-2868.71 ; v1(1190.74,-2257.16) 1190.74,-2244.51 1202.9,-2232.36 U3.42@1202.9,-2214.55 ; J1.3@2118.19,2868.71 2118.19,2831.96 2139.13,2811.02 2173.23,2811.02 2200.64,2838.44 v1(2200.64,2893.56) ; v1(2700.79,1208.66) 2716.19,1193.25 2971.64,1193.25 3021.67,1243.28 MC1.10@3021.67,1315.37 ; v1(2956.94,-2893.57) 2956.94,-2838.45 2984.35,-2811.03 3018.45,-2811.03 3039.39,-2831.96 J5.3@3039.39,-2868.71 ; J2.3@3968.59,2868.71 3968.59,2831.96 3987.98,2812.56 4019.79,2812.56 4069.06,2861.83 4069.06,2884.03 v1(4070.87,2885.83) ; J23.3@6013.94,2869.02 6013.94,2821.26 6024.7,2810.5 6046.83,2810.5 6055.06,2818.72 6055.06,2895.19 6066.74,2906.87 6648.25,2906.87 6787.4,2767.72 6787.4,2327.14 7027.93,2086.61 7271.65,2086.61 7543.31,2358.27 8039.07,2358.27 8255.91,2575.11 8255.91,2698.74 8214.94,2739.7 8214.94,2841.61 8162.86,2893.7 v1(8161.42,2893.7) 8161.42,2895.14 8129.37,2927.19 8076.56,2927.19 8064.19,2914.82 8064.19,2872.03 J8.3@8061.18,2869.02
  L3-SIG w5: v1(1190.74,-2257.16) 1190.74,-2298.99 1145.67,-2344.06 1145.67,-2397.9 1007.13,-2536.45 1007.13,-2698.51 1046.5,-2737.88 1046.5,-2739.41 1047.24,-2740.16 1047.24,-2866.14 1074.67,-2893.57 v1(1106.54,-2893.57) 1137.9,-2862.2 1716.54,-2862.2 1726.67,-2852.07 1773.11,-2852.07 1826.56,-2905.51 2944.99,-2905.51 v1(2956.94,-2893.57) 2988.3,-2862.2 3566.93,-2862.2 3577.07,-2852.07 3698.52,-2852.07 v1(3740.16,-2893.7) ; v1(1822.49,1934.76) 1792.7,1934.76 1779.53,1947.93 1779.53,2089.02 2031.5,2340.99 2031.5,2552.17 2031.5,2657.41 2105.14,2731.06 2105.14,2798.06 v1(2200.64,2893.56) 2202.06,2893.56 2220.04,2911.54 3323.27,2911.54 3378.6,2856.21 4041.24,2856.21 v1(4070.87,2885.83)
  L8-BOT w5: v1(1190.74,-2257.16) 1205.95,-2272.37 1327.25,-2272.37 1367.14,-2232.48 1367.14,-1964.08 1485.76,-1845.46 1485.76,-922.7 2896.23,487.77 2896.23,1096.39 2793.76,1198.86 2712.01,1198.86 2702.2,1208.66 v1(2700.79,1208.66) 2673.23,1236.22 2245.44,1236.22 1978.28,1503.37 1978.28,1778.97 v1(1822.49,1934.76) ; v1(3740.16,-2893.7) 3762.76,-2916.3 9353.82,-2916.3 9407.06,-2863.07 9407.06,-966.9 8757.34,-317.19 8757.34,1230.05 8885.33,1358.04 8885.33,2736.01 8708.45,2912.89 8181.31,2912.89 8162.12,2893.7 v1(8161.42,2893.7)
JTAG_TCK: J3.6 MC1.13 | length 6918.2
  L1-TOP w4.5: MC1.13@3061.04,1558.68 3061.04,1489.64 3071.85,1478.83 3456,1478.83 3480.54,1454.28 3480.54,1414.86 3506.2,1389.2 3567.63,1389.2 3641.73,1315.09 v1(3641.73,1118.83)
  L3-SIG w4.6: J3.6@118.11,-2240.16 157.48,-2200.79 232.28,-2200.79 287.29,-2145.78 288.92,-2144.15 ccw(c285.44,-2140.68) 288.92,-2137.2 284.96,-2133.24 cw(c288.44,-2129.76) 284.96,-2126.28 295.4,-2115.84 cw(c298.87,-2119.32) 302.35,-2115.84 318.69,-2132.18 ccw(c322.17,-2128.7) 325.65,-2132.18 336.09,-2121.74 ccw(c332.61,-2118.26) 336.09,-2114.79 319.75,-2098.45 cw(c323.23,-2094.97) 319.75,-2091.49 330.19,-2081.05 cw(c333.66,-2084.53) 337.14,-2081.05 349.76,-2093.67 ccw(c353.24,-2090.19) 356.72,-2093.67 367.15,-2083.23 ccw(c363.67,-2079.75) 367.15,-2076.27 365.45,-2074.57 cw(c368.93,-2071.1) 365.45,-2067.62 379.92,-2053.15 404.56,-2028.51 404.56,-386.78 1828.9,1037.56 3560.46,1037.56 v1(3641.73,1118.83)
JTAG_TDI: J3.10 MC1.9 | length 6918.2
  L1-TOP w4.5: MC1.9@3021.67,1558.68 3021.67,1486.2 3048.04,1459.83 3448.13,1459.83 3461.54,1446.41 3461.54,1396.21 3495.55,1362.2 3537.86,1362.2 3586.61,1313.45 v1(3586.61,1118.83)
  L3-SIG w4.6: J3.10@118.11,-2082.68 157.48,-2043.31 236.22,-2043.31 239.91,-2039.62 241.54,-2037.99 ccw(c238.06,-2034.51) 241.54,-2031.03 230.82,-2020.31 cw(c234.3,-2016.83) 230.82,-2013.36 241.25,-2002.92 cw(c244.73,-2006.4) 248.21,-2002.92 278.02,-2032.73 ccw(c281.5,-2029.25) 284.98,-2032.73 295.42,-2022.29 ccw(c291.94,-2018.81) 295.42,-2015.33 265.61,-1985.52 cw(c269.09,-1982.04) 265.61,-1978.57 276.04,-1968.13 cw(c279.52,-1971.61) 283,-1968.13 312.81,-1997.94 ccw(c316.29,-1994.46) 319.77,-1997.94 330.21,-1987.5 ccw(c326.73,-1984.02) 330.21,-1980.55 300.4,-1950.73 cw(c303.88,-1947.25) 300.4,-1943.78 310.83,-1933.34 cw(c314.31,-1936.82) 317.79,-1933.34 347.6,-1963.15 ccw(c351.08,-1959.67) 354.56,-1963.15 365,-1952.71 ccw(c361.52,-1949.23) 365,-1945.76 343.37,-1924.13 cw(c346.85,-1920.65) 343.37,-1917.17 353.81,-1906.74 cw(c357.29,-1910.21) 360.77,-1906.74 363.3,-1909.27 ccw(c366.78,-1905.79) 370.26,-1909.27 380.76,-1898.77 387.96,-1891.57 387.96,-379.91 1822.13,1054.27 3522.05,1054.27 v1(3586.61,1118.83)
JTAG_TDO: J3.8 MC1.11 | length 6918.2
  L1-TOP w4.5: MC1.11@3041.35,1558.68 3041.35,1487.53 3059.56,1469.33 3452.06,1469.33 3471.04,1450.35 3471.04,1405.68 3501.17,1375.55 3554.5,1375.55 3613.94,1316.1 v1(3613.94,1149.61)
  L3-SIG w4.6: J3.8@118.11,-2161.42 55.12,-2098.43 55.12,-1914.98 100.01,-1870.08 205.06,-1870.08 207.36,-1870.08 ccw(c207.36,-1865.16) 212.28,-1865.16 212.28,-1853.45 cw(c217.2,-1853.45) 217.2,-1848.53 231.96,-1848.53 cw(c231.96,-1853.45) 236.88,-1853.45 236.88,-1877.57 ccw(c241.8,-1877.57) 241.8,-1882.49 256.56,-1882.49 ccw(c256.56,-1877.57) 261.48,-1877.57 261.48,-1865.16 cw(c266.4,-1865.16) 266.4,-1860.24 281.16,-1860.24 cw(c281.16,-1865.16) 286.08,-1865.16 ccw(c291,-1865.16) 291,-1870.08 305.36,-1870.08 307.09,-1870.08 371.36,-1805.81 371.36,-373.03 1815.25,1070.87 3511.29,1070.87 3590.03,1149.61 v1(3613.94,1149.61)
JTAG_TMS: J3.4 MC1.15 | length 6918.2
  L1-TOP w4.5: MC1.15@3080.72,1558.68 3080.72,1499.15 3091.55,1488.33 3459.93,1488.33 3490.04,1458.22 3490.04,1424.89 3505.48,1409.45 3572.81,1409.45 3673.23,1309.03 v1(3673.23,1118.83)
  L3-SIG w4.6: J3.4@118.11,-2318.9 157.48,-2279.53 240.16,-2279.53 421.26,-2098.43 421.26,-393.7 1835.92,1020.96 3575.36,1020.96 v1(3673.23,1118.83)
M2_ALERT_B: MC2.62 R34.1 U4.4 | length 3256.6
  L1-TOP w5: MC2.62@3730.33,-1558.65 3730.33,-1521.67 3712.6,-1503.94 3519.26,-1503.94 3475.63,-1460.31 3475.63,-1411.45 3500.02,-1387.07 3569.31,-1387.07 3592.05,-1364.33 3592.05,-1240.84 3981.67,-851.21 4905.11,-851.21 4952.29,-898.39 v1(5011.81,-898.39) ; v1(5807.09,-1303.15) 5807.09,-1301.18 5813.93,-1294.34 5816.86,-1294.34 5831.67,-1279.53 U4.4@5863.19,-1279.53
  L3-SIG w5: v1(5011.81,-898.39) 5014.3,-900.88 5026.1,-900.88 5191.4,-1066.18 5279.53,-1066.18 5571.03,-1066.18 5807.09,-1302.24 v1(5807.09,-1303.15)
M2_ALERT_B_3V3: J32.44 R37.1 U4.11 | length 1241.8
  L1-TOP w5: U4.11@6089.57,-1279.53 6093.46,-1283.42 6119.58,-1283.42 6130.5,-1294.34 6138.83,-1294.34 6145.67,-1301.18 R37.1@6145.67,-1303.15 v1(6145.67,-1303.41) ; J32.44@6239.17,-377.95 v1(6291.58,-377.95)
  L3-SIG w5: v1(6145.67,-1303.41) 6192.46,-1303.41 6259.18,-1236.69 6259.18,-1235.69 6259.28,-1235.59 6259.28,-1144.88 6395.29,-1008.87 6395.29,-442.54 6330.71,-377.95 v1(6291.58,-377.95)
M2_CLKREQ_B: MC2.63 U5.2 | length 2740.5
  L1-TOP w5: MC2.63@3750.02,-1315.34 3750.02,-1273.18 3725.16,-1248.32 3725.16,-1192.58 4006.53,-911.21 4828.92,-911.21 4882.27,-964.57 5015.36,-964.57 v1(5035.43,-944.5) ; U5.2@5863.19,-1460.63 v1(5909.45,-1460.63)
  L3-SIG w5: v1(5035.43,-944.5) 5048.5,-944.5 5185.19,-1081.18 5279.53,-1081.18 5557.6,-1081.18 5909.45,-1433.03 v1(5909.45,-1460.63)
M2_CLKREQ_B_3V3: J32.52 R38.1 U5.13 | length 1636.6
  L1-TOP w5: v1(6043.31,-1460.63) U5.13@6089.57,-1460.63 R38.1@6157.48,-1460.63 ; J32.52@6239.17,-299.21 v1(6289.37,-299.21)
  L3-SIG w5: v1(6043.31,-1460.63) 6206.89,-1460.63 6275.28,-1392.24 6275.28,-1151.51 6411.29,-1015.5 6411.29,-435.91 6337.34,-361.95 6330.46,-361.95 6322.83,-354.33 6309.06,-354.33 6289.37,-334.65 v1(6289.37,-299.21)
M2_DEVSLP: MC2.59 U5.4 | length 3038.9
  L1-TOP w5: MC2.59@3513.8,-1315.34 3513.8,-1276.66 3969.25,-821.21 4947.19,-821.21 v1(4988.19,-862.2) ; U5.4@5863.19,-1511.81 v1(5909.45,-1511.81)
  L3-SIG w5: v1(4988.19,-862.2) 4988.19,-953.67 5223.49,-1188.98 5622.05,-1188.98 5870.08,-1437.01 5870.08,-1488.23 5891.18,-1509.32 5906.96,-1509.32 v1(5909.45,-1511.81)
M2_DEVSLP_3V3: J32.38 R41.1 U5.11 | length 1813.6
  L1-TOP w5: v1(6043.31,-1511.81) U5.11@6089.57,-1511.81 6123.33,-1511.81 6143.01,-1531.5 R41.1@6157.48,-1531.5 ; J32.38@6239.17,-437.01 6316.97,-437.01 6346.46,-407.52 v1(6346.46,-322.83)
  L3-SIG w5: v1(6043.31,-1511.81) 6200.97,-1511.81 6307.28,-1405.49 6307.28,-1164.76 6443.29,-1028.75 6443.29,-419.67 v1(6346.46,-322.83)
M2_LED_1_B: MC2.60 U5.5 | length 3347.5
  L1-TOP w5: MC2.60@3513.8,-1558.65 3513.8,-1519.68 3460.63,-1466.52 3460.63,-1405.24 3493.8,-1372.07 3563.1,-1372.07 3577.05,-1358.12 3577.05,-1234.62 3975.46,-836.21 4918.89,-836.21 v1(4964.57,-881.89) ; U5.5@5863.19,-1537.4 v1(5909.45,-1537.4)
  L3-SIG w5: v1(4964.57,-881.89) 4964.57,-951.26 5217.28,-1203.98 5615.83,-1203.98 5854.87,-1443.01 5854.87,-1507.62 5884.65,-1537.4 v1(5909.45,-1537.4)
M2_LED_1_B_3V3: J32.10 R54.1 U5.10 | length 1237.3
  L1-TOP w5: v1(6043.31,-1537.4) 6123.1,-1537.4 6143.86,-1558.17 6150.64,-1558.17 6157.48,-1565.01 R54.1@6157.48,-1566.93 ; J32.10@6239.17,-712.6 v1(6334.65,-712.6)
  L3-SIG w5: v1(6043.31,-1537.4) 6023.62,-1517.72 6023.62,-1433.07 6114.17,-1342.52 6114.17,-1150.28 6163.25,-1101.21 6235.07,-1101.21 6347.29,-988.99 6347.29,-725.25 v1(6334.65,-712.6)
M2_PEDET: MC2.64 U12.3 | length 3599.7
  L1-TOP w5: MC2.64@3750.02,-1558.65 3750.02,-1520.14 3718.81,-1488.94 3525.47,-1488.94 3490.63,-1454.09 3490.63,-1417.67 3506.23,-1402.07 3575.52,-1402.07 3607.05,-1370.54 3607.05,-1247.05 3987.89,-866.21 4863.23,-866.21 v1(4902.53,-905.51) ; U12.3@5863.19,-1718.5 v1(5909.45,-1718.5)
  L3-SIG w5: v1(4902.53,-905.51) 4902.53,-931.65 5204.85,-1233.98 5602.27,-1233.98 5749.52,-1381.23 5749.52,-1558.58 v1(5909.45,-1718.5)
M2_PEDET_3V3: J32.69 R56.1 U12.12 | length 2316.9
  L1-TOP w5: J32.69@5941.93,-131.89 5981.68,-131.89 6023.01,-173.23 v1(6326.77,-173.23) ; v1(6043.31,-1718.5) U12.12@6089.57,-1718.5 6120.95,-1718.5 6145.6,-1743.16 6150.64,-1743.16 6157.48,-1750 R56.1@6157.48,-1751.97
  L3-SIG w5: v1(6043.31,-1718.5) 6339.28,-1422.53 6339.28,-1178.02 6475.29,-1042.01 6475.29,-321.75 v1(6326.77,-173.23)
M2_PER_N0: J32.41 MC3.83 | length 919.5
  L1-TOP w4.2: MC3.83@5594.11,-521.64 5590.57,-518.1 5555.4,-518.1 5537.81,-500.5 5537.81,-357.76 5599.59,-295.98 5747.33,-295.98 5793.5,-249.8 5822.74,-249.8 5822.74,-247.31 v1(5825.21,-244.85) ; J32.41@5941.93,-407.48 5945.47,-403.94 5984.25,-403.94 5989.2,-408.89 v1(5992.13,-408.89)
  L8-BOT w4.2: v1(5825.21,-244.85) 5828.94,-244.85 5833.89,-249.8 5871.19,-249.8 5894.62,-273.23 5938.54,-273.23 6026.57,-361.27 6028.35,-363.04 6028.35,-388.68 6013.09,-403.94 6000.81,-403.94 5995.86,-408.89 v1(5992.13,-408.89)
M2_PER_N1: J32.29 MC3.79 | length 917
  L1-TOP w4.2: MC3.79@5594.11,-265.73 5597.65,-262.19 5669.29,-262.19 5715.21,-262.19 5795.51,-181.89 5814.96,-181.89 5819.91,-186.84 v1(5822.83,-186.84) ; J32.29@5941.93,-525.59 5945.47,-522.05 5998.92,-522.05 6034.62,-522.05 6039.57,-527 v1(6043.31,-527)
  L8-BOT w4.2: v1(5822.83,-186.84) 5826.57,-186.84 5831.52,-181.89 5893.04,-181.89 5915.87,-204.72 6026.57,-315.43 6063.02,-351.87 6063.02,-401.33 6026.57,-437.78 5995.97,-468.39 5995.97,-499.22 6018.79,-522.05 6034.62,-522.05 6039.57,-527 v1(6043.31,-527)
M2_PER_N2: J32.17 MC3.75 | length 1171.6
  L1-TOP w4.2: MC3.75@5594.11,-206.68 5597.65,-203.13 5700.51,-203.13 5792.62,-111.03 5859.74,-111.03 5862.2,-113.49 v1(5862.2,-115.98) ; J32.17@5941.93,-643.7 5945.47,-640.16 6084.15,-640.16 6086.61,-642.62 v1(6086.61,-645.11)
  L8-BOT w4.2: v1(5862.2,-115.98) 5865.94,-115.98 5870.89,-111.03 5889.34,-111.03 5983.04,-204.72 6026.57,-248.26 6111.74,-333.43 6111.74,-520.04 6046.46,-585.33 6046.46,-624.9 6061.71,-640.16 6077.93,-640.16 6082.88,-645.11 v1(6086.61,-645.11)
M2_PER_N3: J32.5 MC3.71 | length 1405.2
  L1-TOP w4.2: MC3.71@5594.11,-147.62 5597.65,-144.08 5696.57,-144.08 5788.68,-51.97 5820.37,-51.97 5822.83,-54.43 v1(5822.83,-56.92) ; J32.5@5941.93,-761.81 5945.47,-758.27 6125.17,-758.27 6130.12,-763.22 v1(6133.86,-763.22)
  L8-BOT w4.2: v1(5822.83,-56.92) 5826.57,-56.92 5831.52,-51.97 5891.41,-51.97 6153.54,-314.11 6153.54,-635.19 6097.39,-691.34 6097.39,-742.32 6113.34,-758.27 6125.17,-758.27 6130.12,-763.22 v1(6133.86,-763.22)
M2_PER_P0: J32.43 MC3.81 | length 919.5
  L1-TOP w4.2: MC3.81@5594.11,-501.95 5590.57,-505.5 5560.62,-505.5 5550.41,-495.28 5550.41,-485.24 5550.41,-458.94 cw(c5555.25,-458.94) 5555.25,-454.1 5572.32,-454.1 ccw(c5572.32,-449.26) 5577.16,-449.26 5577.16,-434.74 ccw(c5572.32,-434.74) 5572.32,-429.9 5555.25,-429.9 cw(c5555.25,-425.06) 5550.41,-425.06 5550.41,-410.54 cw(c5555.25,-410.54) 5555.25,-405.7 5568.87,-405.7 ccw(c5568.87,-400.86) 5573.71,-400.86 5573.71,-386.34 ccw(c5568.87,-386.34) 5568.87,-381.5 5555.25,-381.5 cw(c5555.25,-376.66) 5550.41,-376.66 5550.41,-368.31 5550.41,-362.98 5604.81,-308.58 5752.55,-308.58 5798.72,-262.4 5822.74,-262.4 5825.21,-264.86 v1(5825.21,-267.35) ; J32.43@5941.93,-387.8 5945.47,-391.34 5984.25,-391.34 5989.2,-386.39 v1(5992.13,-386.39)
  L8-BOT w4.2: v1(5825.21,-267.35) 5828.94,-267.35 5833.89,-262.4 5865.97,-262.4 5889.4,-285.83 5933.32,-285.83 6015.75,-368.26 6015.75,-383.46 6007.87,-391.34 6000.81,-391.34 5995.86,-386.39 v1(5992.13,-386.39)
M2_PER_P1: J32.31 MC3.77 | length 917
  L1-TOP w4.2: MC3.77@5594.11,-246.05 5597.65,-249.59 5669.29,-249.59 5709.99,-249.59 5790.29,-169.29 5814.96,-169.29 5819.91,-164.34 v1(5822.83,-164.34) ; J32.31@5941.93,-505.91 5945.47,-509.45 5993.7,-509.45 6034.62,-509.45 6039.57,-504.5 v1(6043.31,-504.5)
  L8-BOT w4.2: v1(5822.83,-164.34) 5826.57,-164.34 5831.52,-169.29 5898.26,-169.29 5933.69,-204.72 6026.57,-297.61 6075.62,-346.65 6075.62,-406.55 6026.57,-455.6 6008.57,-473.6 6008.57,-494 6024.01,-509.45 6034.62,-509.45 6039.57,-504.5 v1(6043.31,-504.5)
M2_PER_P2: J32.19 MC3.73 | length 1171.6
  L1-TOP w4.2: MC3.73@5594.11,-186.99 5597.65,-190.53 5695.29,-190.53 5787.4,-98.43 5859.74,-98.43 5859.74,-95.94 v1(5862.2,-93.48) ; J32.19@5941.93,-624.02 5945.47,-627.56 6084.15,-627.56 6084.15,-625.07 v1(6086.61,-622.61)
  L8-BOT w4.2: v1(5862.2,-93.48) 5865.94,-93.48 5870.89,-98.43 5894.56,-98.43 6000.86,-204.72 6026.57,-230.44 6124.34,-328.21 6124.34,-525.26 6059.06,-590.55 6059.06,-619.68 6066.93,-627.56 6077.93,-627.56 6082.88,-622.61 v1(6086.61,-622.61)
M2_PER_P3: J32.7 MC3.69 | length 1405.2
  L1-TOP w4.2: MC3.69@5594.11,-127.94 5597.65,-131.48 5691.36,-131.48 5783.46,-39.37 5820.37,-39.37 5820.37,-36.88 v1(5822.83,-34.42) ; J32.7@5941.93,-742.13 5945.47,-745.67 6125.17,-745.67 6130.12,-740.72 v1(6133.86,-740.72)
  L8-BOT w4.2: v1(5822.83,-34.42) 5826.57,-34.42 5831.52,-39.37 5896.63,-39.37 6166.14,-308.89 6166.14,-640.4 6109.99,-696.56 6109.99,-737.1 6118.56,-745.67 6125.17,-745.67 6130.12,-740.72 v1(6133.86,-740.72)
M2_PERST_B: MC2.61 U5.3 | length 2810
  L1-TOP w5: MC2.61@3730.33,-1315.34 3730.33,-1278.75 3710.16,-1258.58 3710.16,-1186.37 4000.31,-896.21 4837.15,-896.21 4890.51,-949.57 4983.5,-949.57 v1(5011.81,-921.26) ; U5.3@5863.19,-1486.22 v1(5909.45,-1486.22)
  L3-SIG w5: v1(5011.81,-921.26) 5011.81,-956.08 5151.91,-1096.18 5551.39,-1096.18 5885.83,-1430.62 5885.83,-1462.6 v1(5909.45,-1486.22)
M2_PERST_B_3V3: J32.50 R39.1 U5.12 | length 1662.2
  L1-TOP w5: v1(6043.31,-1486.22) U5.12@6089.57,-1486.22 6127.78,-1486.22 6137.62,-1496.06 R39.1@6157.48,-1496.06 ; J32.50@6239.17,-318.9 v1(6311.02,-318.9)
  L3-SIG w5: v1(6043.31,-1486.22) 6203.93,-1486.22 6291.28,-1398.87 6291.28,-1158.13 6427.29,-1022.12 6427.29,-429.28 6343.96,-345.95 6338.08,-345.95 v1(6311.02,-318.9)
M2_PET_N0: C83.1 MC3.84 | length 818.3
  L1-TOP w4.2: v1(5263.7,-388.81) 5264.65,-389.76 5271.65,-389.76 5282.68,-400.79 5282.68,-501.28 5299.49,-518.1 5347.26,-518.1 MC3.84@5350.8,-521.64 ; v1(5625.98,-382.12) 5629.72,-382.12 5634.67,-377.17 5773.57,-377.17 5805.98,-344.75 5831.93,-344.75 5834.39,-347.21 5834.39,-349.87 C83.1@5842.53,-358.01
  L8-BOT w4.2: v1(5263.7,-388.81) 5266.34,-391.45 5273.34,-391.45 5281.71,-399.82 5421.15,-399.82 5443.8,-377.17 5617.3,-377.17 5622.25,-382.12 v1(5625.98,-382.12)
M2_PET_N0_C: C83.2 J32.47 | length 68.2
  L1-TOP w4.2: C83.2@5880.72,-358.01 5893.97,-344.75 5938.26,-344.75 J32.47@5941.93,-348.43
M2_PET_N1: C81.1 MC3.80 | length 657.8
  L1-TOP w4.2: v1(5688.98,-467.94) 5692.71,-467.94 5697.66,-462.99 5796.85,-462.99 5831.93,-462.99 5834.39,-465.45 5834.39,-468.24 C81.1@5842.53,-476.38
  L8-BOT w4.2: v1(5380.17,-267.23) 5383.91,-267.23 5388.95,-262.19 5608.65,-262.19 5669.29,-322.83 5669.29,-384.97 5649.61,-404.65 5649.61,-444.14 5668.46,-462.99 5680.29,-462.99 5685.24,-467.94 v1(5688.98,-467.94)
M2_PET_N1_C: C81.2 J32.35 | length 68.2
  L1-TOP w4.2: C81.2@5880.72,-476.38 5894.1,-462.99 5938.39,-462.99 J32.35@5941.93,-466.54
M2_PET_N2: C79.1 MC3.76 | length 868.4
  L1-TOP w4.2: v1(5751.97,-585.76) 5755.7,-585.76 5760.65,-580.81 5831.93,-580.81 5834.39,-583.27 5834.39,-585.87 C79.1@5842.53,-594.01
  L8-BOT w4.2: v1(5321.43,-208.18) 5325.17,-208.18 5330.21,-203.13 5612.58,-203.13 5743.31,-333.86 5743.31,-482.68 5711.81,-514.18 5711.81,-561.17 5731.45,-580.81 5743.28,-580.81 5748.23,-585.76 v1(5751.97,-585.76)
M2_PET_N2_C: C79.2 J32.23 | length 68.3
  L1-TOP w4.2: C79.2@5880.72,-594.01 5893.92,-580.81 5938.09,-580.81 J32.23@5941.93,-584.65
M2_PET_N3: C77.1 MC3.72 | length 958.9
  L1-TOP w4.2: v1(5814.96,-704.16) 5818.69,-704.16 5823.65,-699.21 5831.93,-699.21 5834.39,-701.67 5834.39,-704.46 C77.1@5842.53,-712.6
  L8-BOT w4.2: v1(5380.17,-149.12) 5383.91,-149.12 5388.95,-144.08 5628.67,-144.08 5669.29,-184.71 5779.53,-294.94 5795.28,-310.69 5795.28,-610.24 5779.53,-625.98 5766.93,-638.58 5766.93,-674.51 5791.63,-699.21 5806.28,-699.21 5811.23,-704.16 v1(5814.96,-704.16)
M2_PET_N3_C: C77.2 J32.11 | length 68.2
  L1-TOP w4.2: C77.2@5880.72,-712.6 5894.1,-699.21 5938.39,-699.21 J32.11@5941.93,-702.76
M2_PET_P0: C84.1 MC3.82 | length 819
  L1-TOP w4.2: v1(5279.61,-372.9) 5280.56,-373.85 5280.56,-380.85 5295.28,-395.57 5295.28,-496.06 5304.71,-505.5 5347.26,-505.5 MC3.82@5350.8,-501.95 ; v1(5625.98,-359.62) 5629.72,-359.62 5634.67,-364.57 5768.35,-364.57 5800.76,-332.15 5831.93,-332.15 5834.39,-329.69 5834.39,-327.03 C84.1@5842.53,-318.9
  L8-BOT w4.2: v1(5279.61,-372.9) 5282.25,-375.54 5282.25,-382.54 5286.93,-387.22 5337.66,-387.22 5339.76,-387.22 ccw(c5339.76,-382.38) 5344.6,-382.38 5344.6,-377.15 cw(c5349.44,-377.15) 5349.44,-372.31 5363.96,-372.31 cw(c5363.96,-377.15) 5368.8,-377.15 5368.8,-382.38 ccw(c5373.64,-382.38) 5373.64,-387.22 5392.13,-387.22 5415.93,-387.22 5438.58,-364.57 5617.3,-364.57 5622.25,-359.62 v1(5625.98,-359.62)
M2_PET_P0_C: C84.2 J32.49 | length 68.1
  L1-TOP w4.2: C84.2@5880.72,-318.9 5893.97,-332.15 5938.52,-332.15 J32.49@5941.93,-328.74
M2_PET_P1: C82.1 MC3.78 | length 657.8
  L1-TOP w4.2: v1(5688.98,-445.44) 5692.71,-445.44 5697.66,-450.39 5802.07,-450.39 5831.93,-450.39 5834.39,-447.93 5834.39,-445.14 C82.1@5842.53,-437.01
  L8-BOT w4.2: v1(5380.17,-244.55) 5383.91,-244.55 5388.95,-249.59 5613.87,-249.59 5681.89,-317.62 5681.89,-390.18 5669.29,-402.78 5662.21,-409.87 5662.21,-438.92 5673.68,-450.39 5680.29,-450.39 5685.24,-445.44 v1(5688.98,-445.44)
M2_PET_P1_C: C82.2 J32.37 | length 68.2
  L1-TOP w4.2: C82.2@5880.72,-437.01 5894.1,-450.39 5938.39,-450.39 J32.37@5941.93,-446.85
M2_PET_P2: C80.1 MC3.74 | length 868.4
  L1-TOP w4.2: v1(5751.97,-563.26) 5755.7,-563.26 5760.65,-568.21 5831.93,-568.21 5834.39,-565.75 5834.39,-563.14 C80.1@5842.53,-555.01
  L8-BOT w4.2: v1(5321.43,-185.49) 5325.17,-185.49 5330.21,-190.53 5617.8,-190.53 5755.91,-328.64 5755.91,-487.9 5724.41,-519.4 5724.41,-555.95 5736.67,-568.21 5743.28,-568.21 5748.23,-563.26 v1(5751.97,-563.26)
M2_PET_P2_C: C80.2 J32.25 | length 68
  L1-TOP w4.2: C80.2@5880.72,-555.01 5893.92,-568.21 5938.68,-568.21 J32.25@5941.93,-564.96
M2_PET_P3: C78.1 MC3.70 | length 958.9
  L1-TOP w4.2: v1(5814.96,-681.66) 5818.69,-681.66 5823.65,-686.61 5831.93,-686.61 5834.39,-684.15 5834.39,-681.36 C78.1@5842.53,-673.23
  L8-BOT w4.2: v1(5380.17,-126.44) 5383.91,-126.44 5388.95,-131.48 5633.88,-131.48 5669.29,-166.89 5779.53,-277.12 5807.88,-305.47 5807.88,-615.46 5779.53,-643.8 5779.53,-669.29 5796.85,-686.61 5806.28,-686.61 5811.23,-681.66 v1(5814.96,-681.66)
M2_PET_P3_C: C78.2 J32.13 | length 68.2
  L1-TOP w4.2: C78.2@5880.72,-673.23 5894.1,-686.61 5938.39,-686.61 J32.13@5941.93,-683.07
M2_PEWAKE_B: MC2.65 U12.4 | length 2902.5
  L1-TOP w5: MC2.65@3769.7,-1315.34 3769.7,-1271.65 3740.16,-1242.11 3740.16,-1198.79 4012.74,-926.21 4814.98,-926.21 v1(4868.1,-979.32) ; U12.4@5863.19,-1744.09 v1(5909.45,-1744.09)
  L3-SIG w5: v1(4868.1,-979.32) 4928.99,-979.32 5198.64,-1248.98 5596.05,-1248.98 5734.52,-1387.44 5734.52,-1569.17 v1(5909.45,-1744.09)
M2_PEWAKE_B_3V3: J32.54 R57.1 U12.11 | length 1895.1
  L1-TOP w5: v1(6043.31,-1744.1) U12.11@6089.57,-1744.09 6121.72,-1744.09 6130.84,-1753.21 6130.84,-1776.51 6141.73,-1787.4 R57.1@6157.48,-1787.4 ; J32.54@6239.17,-279.53 6279.95,-279.53 6285.85,-273.62 v1(6289.37,-273.62)
  L3-SIG w5: v1(6043.31,-1744.1) 6007.62,-1708.41 6007.62,-1426.44 6098.17,-1335.89 6098.17,-1143.66 6156.62,-1085.21 6228.44,-1085.21 6331.29,-982.36 6331.29,-740.74 6314.94,-724.39 6314.94,-471.29 6267.72,-424.07 6267.72,-295.28 v1(6289.37,-273.62)
M2_REFCLK_N: J32.53 R60.2 R61.1 | length 1723.5
  L1-TOP w4.2: J32.53@5941.93,-289.37 5938.39,-285.83 5888.92,-285.83 5867.13,-264.05 5867.13,-223.71 5894.78,-196.06 6304.43,-196.06 6382.68,-274.31 6382.68,-485.83 6356.95,-511.56 6356.95,-628.1 6382.68,-653.83 6382.68,-843.8 6327.23,-899.25 6203.11,-899.25 6174.02,-928.35 6174.02,-991.23 6130.14,-1035.11 6112.42,-1035.11 6109.95,-1037.57 6109.95,-1038.46 6102.21,-1046.2 R60.2@6100.24,-1046.2 6098.28,-1046.2 6090.53,-1038.46 6090.53,-1038.29 6088.07,-1035.83 6077.13,-1035.83 6074.67,-1038.29 6074.67,-1040.43 R61.1@6066.93,-1048.17
M2_REFCLK_P: J32.55 R40.1 R59.2 | length 1724.4
  L1-TOP w4.2: J32.55@5941.93,-269.69 5938.39,-273.23 5894.13,-273.23 5879.73,-258.83 5879.73,-228.93 5900,-208.66 6299.21,-208.66 6370.08,-279.53 6370.08,-480.61 6344.35,-506.34 6344.35,-532.64 cw(c6339.51,-532.64) 6339.51,-537.48 6324.19,-537.48 ccw(c6324.19,-542.32) 6319.35,-542.32 6319.35,-556.84 ccw(c6324.19,-556.84) 6324.19,-561.68 6339.51,-561.68 cw(c6339.51,-566.52) 6344.35,-566.52 6344.35,-581.04 cw(c6339.51,-581.04) 6339.51,-585.88 6324.19,-585.88 ccw(c6324.19,-590.72) 6319.35,-590.72 6319.35,-605.24 ccw(c6324.19,-605.24) 6324.19,-610.08 6339.51,-610.08 cw(c6339.51,-614.92) 6344.35,-614.92 6344.35,-623.68 6344.35,-633.32 6370.08,-659.05 6370.08,-838.58 6322.01,-886.65 6197.89,-886.65 6161.42,-923.13 6161.42,-986.01 6124.92,-1022.51 6112.42,-1022.51 6109.95,-1020.05 6109.95,-1019.16 6102.21,-1011.41 R59.2@6100.24,-1011.41 6098.28,-1011.41 6090.53,-1019.16 6090.53,-1020.05 6087.35,-1023.23 6077.13,-1023.23 6074.67,-1020.77 6074.67,-1018.63 R40.1@6066.93,-1010.89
